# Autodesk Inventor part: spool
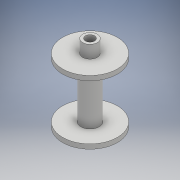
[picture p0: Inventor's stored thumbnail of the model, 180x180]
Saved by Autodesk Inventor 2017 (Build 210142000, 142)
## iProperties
Created: 2017-04
Part Number: spool
Material: Generic
Document SubType Name: Modeling
Designer: s4321966
Density: 1 g/cm^3
Appearance: Default
Author: s4321966
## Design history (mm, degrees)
sketch "Sketch1"
  geometry: L1 (0, 0)-(2.5, 0); L2 (2.5, 0)-(2.5, -7); L3 (0, 0)-(4, 0); L4 (4, 0)-(4, -7); L5 (2.5, -7)-(4, -7); L6 (4, -7)-(4, 0); L7 (4, 0)-(2.5, 0); L8 (2.5, 0)-(2.5, -7); L9 (2.5, -7)-(15, -7); L10 (15, -7)-(15, -9.5); L11 (15, -9.5)-(2.5, -9.5); L12 (2.5, -9.5)-(2.5, -7); L13 (2.5, -9.5)-(5, -9.5); L14 (5, -9.5)-(5, -39.5); L15 (5, -39.5)-(2.5, -39.5); L16 (2.5, -39.5)-(2.5, -9.5); L17 (5, -24.5)-(-8.966, -24.5); L18 (2.5, -39.5)-(5, -39.5); L19 (15, -39.5)-(2.5, -39.5); L20 (2.5, -42)-(15, -42); L21 (15, -42)-(15, -39.5); L22 (2.5, -39.5)-(2.5, -42); L23 (2.5, -42)-(4, -42); L24 (2.5, -49)-(2.5, -42); L25 (4, -42)-(4, -49); L26 (4, -49)-(2.5, -49); L27 (2.5, -49)-(2.5, -42); L28 (0, -49)-(2.5, -49); L29 (0, -49)-(4, -49); L30 (4, -49)-(4, -42); L31 (0, 0)-(0, -54.882)
  constraints: 62 end point, 9 symmetric about line, 6 horizontal, 6 parallel, 5 perpendicular, 1 midpoint, 1 vertical
  dimensions: "d0" = 2.5 distance of L1.start L1.end; "d1" = 7 distance of L1.end L2.end; "d2" = 90 deg angle of L1 L2 (derived); "d3" = 4 distance of L1.start L3.end; "d4" = 12.5 distance of L10.end L11.end; "d5" = 2.5 distance of L9.end L10.end; "d6" = 2.5 distance of L14.end L15.end; "d7" = 30 distance of L13.end L14.end
revolve "Revolution1" sketch "Sketch1" stored, may be unused: angle "d8" = 90 deg
sketch "Sketch2"
  geometry: L1 (0, 0)-(0, -15); L2 (0, 0)-(15, 0); C1 r 1.25 at (0, -15)
  constraints: 4 end point, 1 centre point, 1 coincident, 1 horizontal, 1 perpendicular, 1 vertical
  dimensions: "d9" = 15 distance of L1.start L1.end; "d10" = 90 deg angle of L1 L2 (derived); "d11" = 2.5 diameter of C1
extrude "Extrusion1" cut sketch "Sketch2" distance "d12" = 10; taper "d13" = 0 deg
body "Solid1"
